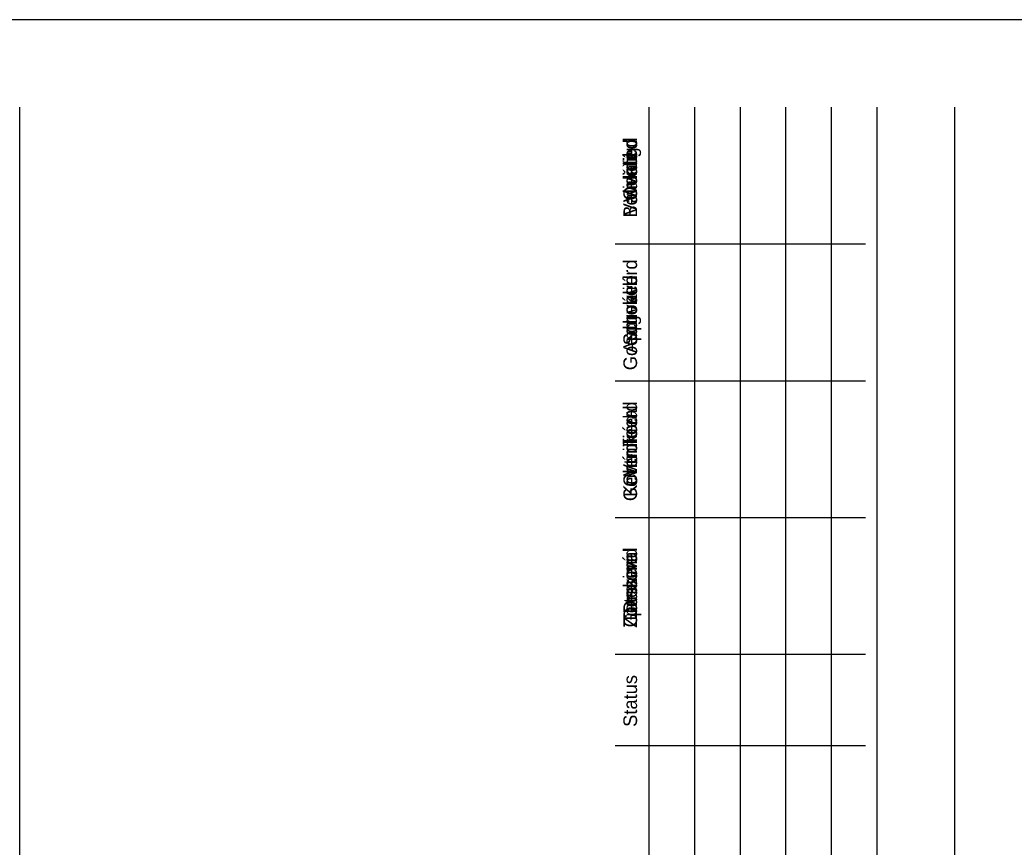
# Model space of a CAD drawing. Extents: x -932963 to -932666, y -737039 to -736000.
# Drawn here: x -932796.6213 to -932796.5667, y -736668.9396 to -736668.8942 of the extents above; entities that cross this region are included whole.
import ezdxf

# ---------------------------------------------------------------- set-up
doc = ezdxf.new("R2010")
doc.units = 0
for name, color, linetype in [('Border', 7, 'Continuous'), ('Border_TextCZ', 7, 'Continuous'), ('Border_TextFR', 7, 'Continuous'), ('Border_TextNL', 7, 'Continuous'), ('Border_TextUK', 7, 'Continuous')]:
    doc.layers.add(name, color=color, linetype=linetype)

# ---------------------------------------------------------------- blocks, each defined once
blk = doc.blocks.new('A0_v03_CZ_1')
at = {"layer": 'Border'}
blk.add_line((0.98758, 0.15206), (1.17758, 0.15206), dxfattribs=at)
blk.add_lwpolyline([(0, 0), (1.188, 0), (1.188, 0.84), (0, 0.84)], close=True, dxfattribs=at)
for points in [[(0.98758, 0.22115), (1.17842, 0.22115)], [(1.10842, 0.15581), (1.10842, 0.12831)], [(1.11842, 0.15581), (1.11842, 0.12831)], [(1.13342, 0.15581), (1.13342, 0.12831)], [(1.14842, 0.15581), (1.14842, 0.12831)], [(1.16342, 0.15581), (1.16342, 0.12831)], [(0.98758, 0.15206), (1.17842, 0.15206)], [(0.98758, 0.14706), (1.17842, 0.14706)], [(0.98758, 0.14206), (1.17842, 0.14206)], [(0.98758, 0.13706), (1.17842, 0.13706)], [(0.98758, 0.13206), (1.17842, 0.13206)], [(0.98758, 0.12706), (1.17842, 0.12706)], [(0.98758, 0.1185), (1.17842, 0.1185)]]:
    blk.add_lwpolyline(points, dxfattribs=at)
at = {"layer": 'Border_TextCZ'}
for s, p in [('Schválil', (1.15231, 0.1534)), ('Ověřil', (1.16818, 0.1534)), ('Status', (1.11045, 0.1534)), ('Zpracoval', (1.12132, 0.1534)), ('Kontroloval', (1.13568, 0.1534))]:
    blk.add_text(s, height=0.0015, dxfattribs=at).set_placement(p)
at = {"layer": 'Border_TextFR'}
for s, p in [('Dessiné', (1.12213, 0.1534)), ('Vérifié', (1.13795, 0.1534)), ('Approuvé', (1.15143, 0.1534)), ('Validé', (1.168, 0.1534)), ('Status', (1.11045, 0.1534))]:
    blk.add_text(s, height=0.0015, dxfattribs=at).set_placement(p)
at = {"layer": 'Border_TextNL'}
for s, p in [('Status', (1.11045, 0.1534)), ('Getekend', (1.12137, 0.1534)), ('Geverifieerd', (1.13521, 0.1534)), ('Goedgekeurd', (1.14957, 0.1534)), ('Bevestigd', (1.16631, 0.1534))]:
    blk.add_text(s, height=0.0015, dxfattribs=at).set_placement(p)
at = {"layer": 'Border_TextUK'}
for s, p in [('Status', (1.11045, 0.1534)), ('Drawn', (1.12289, 0.1534)), ('Checked', (1.13678, 0.1534)), ('Approved', (1.15143, 0.1534)), ('Validated', (1.16655, 0.1534))]:
    blk.add_text(s, height=0.0015, dxfattribs=at).set_placement(p)

msp = doc.modelspace()

# ---------------------------------------------------------------- block references
at = {"layer": 'Border', "xscale": 0.5, "yscale": 0.5, "rotation": 90}
msp.add_blockref('A0_v03_CZ_1', (-932796.510744, -736669.488249), dxfattribs=at)

doc.saveas('drawing.dxf')
